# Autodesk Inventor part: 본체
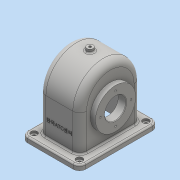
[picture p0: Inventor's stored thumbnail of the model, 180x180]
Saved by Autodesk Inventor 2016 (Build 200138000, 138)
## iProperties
Created: 2018-11
Part Number: 본체
Material: 일반
Document SubType Name: Modeling
Designer: user
Density: 1 g/cm^3
Appearance: 기본값
Author: user
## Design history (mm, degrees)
sketch "스케치1"
  geometry: L1 (-55, -75)-(55, -75); L2 (55, -75)-(55, 75); L3 (55, 75)-(-55, 75); L4 (-55, 75)-(-55, -75); L5 (-55, -75)-(55, 75); L6 (55, -75)-(-55, 75); 1 further point
  constraints: 12 end point, 2 midpoint, 2 parallel, 1 horizontal, 1 perpendicular
  dimensions: "d0" = 110 distance of L3.end L2.end; "d1" = 150 distance of L2.end L1.end
extrude "돌출1" new body sketch "스케치1" distance "d2" = 10; taper "d3" = 0 deg
sketch "스케치2"
  geometry: L1 (-38.5, 58)-(38.5, 58); L2 (38.5, 58)-(38.5, -58); L3 (38.5, -58)-(-38.5, -58); L4 (-38.5, -58)-(-38.5, 58); L5 (-38.5, 58)-(38.5, -58); L6 (38.5, 58)-(-38.5, -58); 1 further point
  constraints: 12 end point, 2 midpoint, 2 parallel, 1 horizontal, 1 perpendicular
  dimensions: "d4" = 77 distance of L2.end L3.end; "d5" = 116 distance of L1.end L2.end
extrude "돌출2" join sketch "스케치2" distance "d6" = 126; taper "d7" = 0 deg
fillet "모깎기1" dims "d8" = 58
feature "쉘1" dims "d11" = 6, "d12" = 10, "d13" = 5
sketch "스케치4"
  geometry: L1 (-10, 133)-(-10, -17) reference; C1 r 38 at (55, 58); 2 further points
  constraints: 1 centre point, 1 horizontal alignment, 1 midpoint
  dimensions: "d14" = 76 diameter of C1; "d15" = 65 distance from line of L1 C1.centre
extrude "돌출3" join sketch "스케치4" distance "d16" = 5; taper "d18" = 0 deg; dims "d17" = 19, "d19" = 0
sketch "스케치6"
  geometry: L1 (-65, 75)-(-65, -75) reference; C1 r 20 at (0, 0); 2 further points
  constraints: 1 centre point, 1 horizontal alignment, 1 midpoint
  dimensions: "d21" = 40 diameter of C1; "d22" = 65 distance from line of L1 C1.centre
extrude "돌출4" cut sketch "스케치6" distance "d23" = 24; taper "d24" = 0 deg
sketch "스케치7"
  geometry: L1 (10, -17)-(10, 133) reference; C1 r 38 at (-55, 58); 2 further points
  constraints: 1 centre point, 1 horizontal alignment, 1 midpoint
  dimensions: "d25" = 76 diameter of C1; "d26" = 65 distance from line of L1 C1.centre
extrude "돌출5" join sketch "스케치7" distance "d27" = 10; taper "d28" = 0 deg
sketch "스케치8"
  geometry: L1 (65, -75)-(65, 75) reference; C1 r 20 at (0, 0); 1 further point
  constraints: 1 centre point, 1 horizontal alignment
  dimensions: "d29" = 40 diameter of C1; "d30" = 65 distance from line of L1 C1.centre
extrude "돌출6" cut sketch "스케치8" distance "d31" = 15; taper "d32" = 0 deg
fillet "모깎기2" dims "d33" = 12
sketch "스케치9"
  geometry: A1 r 12 centre (43, -63) between (43, -75) and (55, -63) reference; 2 further points
  constraints: 1 coincident
hole "구멍1" sketch "스케치9" at (43, -63) diameter "d34" = 5; stored, may be unused: countersink angle "d38" = 90 deg, drill point angle "d40" = 118 deg; dims "d35" = 6, "d36" = 12, "d37" = 4, "d39" = 8
sketch "스케치10"
  geometry: L1 (65, -63)-(65, 63) reference; C1 r 38 at (0, 0) reference; 3 further points
  constraints: 1 horizontal alignment, 1 midpoint
  dimensions: "d42" = 29 distance of C1.centre point (-29, 0)
hole "구멍2" sketch "스케치10" at (-29, 0) diameter "d43" = 3.242; stored, may be unused: countersink angle "d47" = 90 deg, drill point angle "d49" = 118 deg; dims "d44" = 8, "d45" = 4, "d46" = 2, "d48" = 11.8
fillet "모깎기3" dims "d67" = 13
fillet "모깎기4" dims "d68" = 3
fillet "모깎기5" dims "d69" = 8
fillet "모깎기6" dims "d70" = 3
fillet "모깎기7" dims "d71" = 3
sketch "스케치15"
  geometry: C1 r 20 at (13, 0) reference; C2 r 20 at (13, 0) reference; C3 r 28 at (13, 0); 1 further point
  constraints: 1 centre point, 1 coincident
  dimensions: "d73" = 56 diameter of C3
extrude "돌출8" join sketch "스케치15" distance "d74" = 14; taper "d75" = 0 deg
feature "면 기울기3" dims angle "d76" = 40 deg
sketch "스케치16"
  geometry: C1 r 20 at (0, 0) reference; 1 further point
extrude "돌출9" cut sketch "스케치16" stored distance "d77" = 14; taper "d78" = 0 deg
node "작업 평면2"
sketch "스케치17"
  geometry: C1 r 6 at (0, 0); 1 further point
  constraints: 1 centre point, 1 coincident
  dimensions: "d82" = 12 diameter of C1
extrude "돌출10" join sketch "스케치17" stored distance "d83" = 14; taper "d84" = 5 deg
sketch "스케치18"
  geometry: 2 further points
  constraints: 1 coincident
hole "구멍4" sketch "스케치18" at (0, 0) diameter "d85" = 4.459; stored, may be unused: countersink angle "d89" = 90 deg, drill point angle "d91" = 118 deg; dims "d86" = 12, "d87" = 4, "d88" = 2, "d90" = 12
fillet "모깎기8" dims "d92" = 3
chamfer "모따기1" distance "d93" = 1; stored, may be unused: second distance "d94" = 2, angle "d95" = 45 deg
sketch "스케치19"
  geometry: L1 (-17.5, -78)-(68.5, -78) reference; 3 further points
  constraints: 1 midpoint, 1 vertical alignment, 1 other
  dimensions: "d96" = 40 distance from line of L1 point (25.5, -38)
feature "엠보싱2" sketch "스케치19" dims "d97" = 0.5, "d98" = 0
node "솔리드1"
mirror "대칭1"
mirror "대칭2"
pattern_circular "원형 패턴1" dims angle "d51" = 360 deg
mirror "대칭3"
other parameters: "d81" = 142
